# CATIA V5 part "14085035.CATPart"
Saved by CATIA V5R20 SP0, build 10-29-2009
Part number: 14085035
Definition: NONE
Nomenclature: 14085035
Source: Unknown
Description: 14085035
Bounding box of the stored display mesh (mm): x -17.5 to 70, y -56.5 to 46.401, z -46.6 to 46.6
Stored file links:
  C:\Users\Utente\Desktop\IO LAVORO\3D X SITO CF\X SITO\PLASTICA\RF2\14085035.CATPart
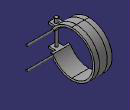
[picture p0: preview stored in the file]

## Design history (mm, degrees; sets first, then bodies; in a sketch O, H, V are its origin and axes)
Body1 "14085035" (main body)
  Solid1: solid without history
